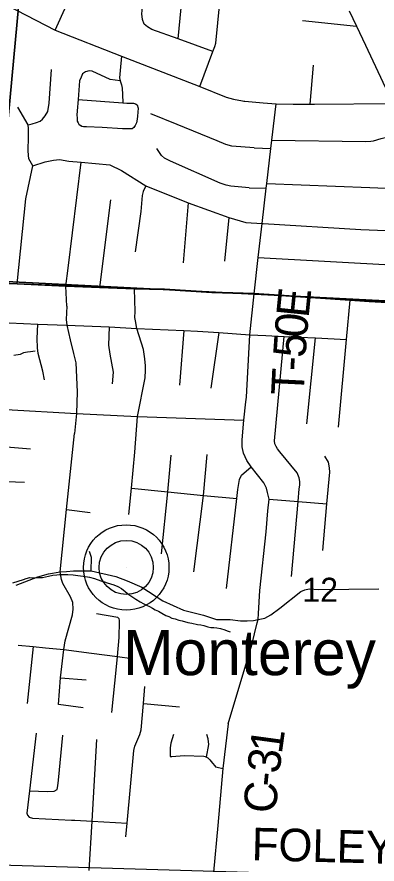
# Model space of a CAD drawing. Extents: x 0 to 34, y -2 to 22.
# Drawn here: x 5.292 to 5.919, y 16.731 to 18.207 of the extents above; entities that cross this region are included whole.
import ezdxf

# ---------------------------------------------------------------- set-up
doc = ezdxf.new("R2010")
doc.units = 0
for name, color, linetype in [('GM_X_City_Street', 7, 'Continuous'), ('GM_X_County_Road', 7, 'Continuous'), ('GM_X_County_Road_Text', 7, 'Continuous'), ('GM_X_Minor_River', 7, 'Continuous'), ('GM_X_Rail_Line', 7, 'Continuous'), ('GM_X_Section', 7, 'Continuous'), ('GM_X_Section_Text', 7, 'Continuous'), ('GM_X_State_Route', 7, 'Continuous'), ('GM_X_Township_Road', 7, 'Continuous'), ('GM_X_Township_Road_Text', 7, 'Continuous'), ('GM_X_Unincorporated', 7, 'Continuous'), ('GM_X_Unincorporated_Location', 7, 'Continuous'), ('GM_X_Unincorporated_Text', 7, 'Continuous')]:
    doc.layers.add(name, color=color, linetype=linetype)

msp = doc.modelspace()

# ---------------------------------------------------------------- linework, layer by layer
at = {"layer": 'GM_X_City_Street'}
for p, q in [((5.7895, 18.2011), (5.8832, 18.1912)), ((5.8026, 18.0553), (5.8087, 18.1234)), ((5.7049, 17.979), (5.7342, 17.9778)), ((5.6962, 17.9094), (5.7262, 17.9092)), ((5.7122, 17.7882), (6.0972, 17.7666)), ((5.5827, 17.6607), (5.5752, 17.5656)), ((5.7966, 17.4983), (5.8122, 17.6478))]:
    msp.add_line(p, q, dxfattribs=at)
for points in [[(5.7359, 17.9926), (5.8989, 17.9905), (5.9083, 17.9906), (5.9131, 17.9915), (5.9263, 17.9953), (5.9405, 17.999), (5.9682, 18.0148)], [(5.7271, 17.917), (5.9063, 17.9098), (5.9481, 17.9081), (5.9631, 17.9113), (5.9865, 17.9193), (6.0116, 17.9322)], [(5.6904, 17.8489), (5.7191, 17.8472), (5.7208, 17.8471), (5.8908, 17.8371), (6.0646, 17.83)], [(5.8521, 17.4924), (5.8661, 17.6452), (5.8723, 17.7135)], [(5.3792, 17.7031), (5.378, 17.6797), (5.3788, 17.6699), (5.3851, 17.6445), (5.3908, 17.6205), (5.3946, 17.6045), (5.397, 17.5536), (5.3959, 17.516), (5.3921, 17.4811)], [(5.4869, 17.3399), (5.4916, 17.3861), (5.4976, 17.4485), (5.5019, 17.5109), (5.5156, 17.5784), (5.5158, 17.5914), (5.5158, 17.5991), (5.5147, 17.6113), (5.5123, 17.6276), (5.501, 17.6644), (5.4984, 17.6774), (5.4976, 17.6834), (5.4978, 17.6939)], [(5.2288, 17.6765), (5.2532, 17.6752), (5.3283, 17.6719), (5.3788, 17.6699), (5.4526, 17.667), (5.501, 17.6644), (5.5827, 17.6607), (5.6067, 17.6595)], [(5.3403, 17.5748), (5.3374, 17.5901), (5.3292, 17.6209), (5.3281, 17.6308), (5.3275, 17.6466), (5.3283, 17.6719)], [(5.4526, 17.667), (5.4514, 17.6355), (5.4537, 17.6195), (5.4599, 17.588), (5.458, 17.5681)], [(5.7257, 17.6521), (5.7576, 17.6506), (5.8122, 17.6478), (5.8661, 17.6452)], [(5.7701, 17.232), (5.7815, 17.3629), (5.7835, 17.3849), (5.7844, 17.3911), (5.7848, 17.3975), (5.7834, 17.4041), (5.7803, 17.4127), (5.7496, 17.4494), (5.7455, 17.4543), (5.7434, 17.4585), (5.7414, 17.4634), (5.7406, 17.4686), (5.7576, 17.6506)], [(5.2736, 17.5232), (5.3959, 17.516), (5.5019, 17.5109), (5.6874, 17.5046)], [(5.544, 17.2712), (5.5546, 17.3795), (5.5606, 17.4432)], [(5.6004, 17.24), (5.6167, 17.3731), (5.6231, 17.4446)], [(5.8245, 17.2773), (5.8318, 17.3586), (5.8367, 17.4141), (5.8365, 17.4215), (5.8343, 17.4311), (5.8282, 17.442)], [(5.6571, 17.2108), (5.6752, 17.3677), (5.6768, 17.3839), (5.6796, 17.4012), (5.6834, 17.4086), (5.6998, 17.4229)], [(5.4916, 17.3861), (5.5546, 17.3795), (5.6167, 17.3731), (5.6752, 17.3677)], [(5.7313, 17.3667), (5.7815, 17.3629), (5.8318, 17.3586)]]:
    msp.add_lwpolyline(points, dxfattribs=at)
at = {"layer": 'GM_X_County_Road'}
for p, q in [((5.7432, 18.0559), (5.7729, 18.0556)), ((5.6417, 16.798), (5.6344, 16.7168))]:
    msp.add_line(p, q, dxfattribs=at)
for points in [[(5.192, 18.2677), (5.2571, 18.2366), (5.359, 18.1842), (5.4743, 18.1391), (5.6103, 18.0859), (5.6567, 18.0677), (5.6692, 18.064), (5.685, 18.0612)], [(5.685, 18.0612), (5.6869, 18.0608), (5.6892, 18.0604), (5.7208, 18.0578), (5.7432, 18.0559)], [(5.7729, 18.0556), (5.8026, 18.0553), (5.8104, 18.0553), (5.9463, 18.0565)], [(3.699, 17.9089), (3.9116, 17.8892), (3.995, 17.8815), (4.2231, 17.8563), (4.3328, 17.8445), (4.4265, 17.8357), (4.5119, 17.8261), (4.6385, 17.8125), (4.7305, 17.8021), (4.8416, 17.7902), (4.8921, 17.785), (5.1052, 17.7555), (5.1438, 17.7513), (5.1995, 17.7504), (5.2414, 17.7441), (5.2926, 17.7419), (5.3775, 17.7381), (5.4364, 17.7355), (5.4969, 17.7336), (5.5492, 17.7321), (5.6317, 17.7272), (5.6868, 17.7254)], [(5.6868, 17.7254), (5.7049, 17.7248), (5.7344, 17.7228)], [(5.7344, 17.7228), (5.8723, 17.7135), (5.9052, 17.7112), (6.0417, 17.704), (6.103, 17.7007), (6.1354, 17.7008)], [(5.2909, 17.2169), (5.3286, 17.2315), (5.3472, 17.2365), (5.3674, 17.2401), (5.3784, 17.2409), (5.3906, 17.2419), (5.4211, 17.2417), (5.4646, 17.2317), (5.4843, 17.2242), (5.5095, 17.2135), (5.5459, 17.1898), (5.5824, 17.1732), (5.617, 17.1645), (5.6397, 17.1568), (5.6636, 17.1572), (5.6816, 17.1547), (5.6826, 17.1547)], [(5.6826, 17.1547), (5.6927, 17.1546), (5.7038, 17.1555), (5.7122, 17.1571), (5.7237, 17.1596), (5.7341, 17.1651), (5.7499, 17.1765), (5.7866, 17.2056), (5.7936, 17.2089), (5.8012, 17.2102), (5.8175, 17.2094), (5.9224, 17.2104)], [(5.6599, 16.9751), (5.6505, 16.8973), (5.6417, 16.798)]]:
    msp.add_lwpolyline(points, dxfattribs=at)
at = {"layer": 'GM_X_Minor_River'}
for points in [[(5.324, 17.6245), (5.3156, 17.6236), (5.3107, 17.623), (5.3038, 17.6216), (5.298, 17.6191), (5.2869, 17.6171)], [(5.2849, 17.2211), (5.2941, 17.2239), (5.3037, 17.227), (5.3083, 17.2284), (5.3145, 17.2305), (5.3232, 17.2299), (5.3308, 17.2305), (5.3365, 17.2303), (5.3472, 17.2323), (5.3545, 17.234), (5.3614, 17.2349), (5.3663, 17.2352), (5.3808, 17.2355), (5.3899, 17.2349), (5.3982, 17.2339), (5.4073, 17.2325), (5.4183, 17.2307), (5.427, 17.2285), (5.4319, 17.2269), (5.4402, 17.224), (5.4447, 17.2227), (5.4492, 17.2211), (5.4609, 17.2177), (5.4681, 17.2148), (5.4741, 17.2112), (5.4804, 17.2061), (5.4871, 17.2006), (5.4938, 17.1958), (5.4994, 17.1926), (5.5065, 17.1879), (5.5133, 17.1846), (5.5178, 17.1818), (5.523, 17.1794), (5.5279, 17.177), (5.5328, 17.1738), (5.5384, 17.1713), (5.5444, 17.1681), (5.5515, 17.1641), (5.5568, 17.1621), (5.562, 17.1593), (5.5677, 17.158), (5.5741, 17.1559), (5.5798, 17.1546), (5.5896, 17.152), (5.5964, 17.1507), (5.6066, 17.1485), (5.6123, 17.1479), (5.6176, 17.1463), (5.6247, 17.1442), (5.6297, 17.1433), (5.635, 17.1431), (5.6403, 17.1422), (5.6463, 17.1413), (5.6539, 17.1388), (5.6584, 17.1375), (5.6633, 17.1355)]]:
    msp.add_lwpolyline(points, dxfattribs=at)
at = {"layer": 'GM_X_Rail_Line'}
for points in [[(6.0414, 17.7045), (5.905, 17.7117), (5.8721, 17.714), (5.7046, 17.7254), (5.6315, 17.7277), (5.5489, 17.7326), (5.4967, 17.7342), (5.4361, 17.736), (5.3773, 17.7386), (5.2924, 17.7424), (5.2412, 17.7447), (5.1993, 17.7509), (5.1435, 17.7518), (5.105, 17.756), (4.8918, 17.7856), (4.8414, 17.7907), (4.7302, 17.8027), (4.6382, 17.813), (4.5117, 17.8266), (4.4263, 17.8362), (4.3326, 17.8451)], [(4.3326, 17.8451), (4.4263, 17.8362), (4.5117, 17.8266), (4.6382, 17.813), (4.7302, 17.8027), (4.8414, 17.7907), (4.8918, 17.7856), (5.105, 17.756), (5.1435, 17.7518), (5.1993, 17.7509), (5.2412, 17.7447), (5.2924, 17.7424), (5.3773, 17.7386), (5.4361, 17.736), (5.4967, 17.7342), (5.5489, 17.7326), (5.6315, 17.7277), (5.7046, 17.7254), (5.8721, 17.714), (5.905, 17.7117), (6.0414, 17.7045)]]:
    msp.add_lwpolyline(points, dxfattribs=at)
at = {"layer": 'GM_X_Section'}
for points in [[(4.3356, 18.8839), (5.3451, 18.7715), (5.25, 17.7471), (4.2197, 17.8557)], [(6.3407, 18.6907), (6.241, 17.6971), (5.25, 17.7471), (5.3451, 18.7715)], [(5.25, 17.7471), (6.241, 17.6971), (6.1288, 16.703), (5.1427, 16.732)]]:
    msp.add_lwpolyline(points, close=True, dxfattribs=at)
at = {"layer": 'GM_X_State_Route'}
msp.add_lwpolyline([(5.8704, 18.218), (5.8832, 18.1912), (5.8991, 18.1582), (5.9463, 18.0565), (5.9507, 18.0481), (5.9682, 18.0148), (5.9885, 17.9762), (6.0116, 17.9322), (6.0145, 17.9267), (6.0324, 17.8927), (6.0646, 17.83), (6.0972, 17.7666), (6.1139, 17.7342), (6.1354, 17.7008), (6.1496, 17.6764), (6.1909, 17.6197), (6.2168, 17.5842), (6.2224, 17.5778), (6.2376, 17.5718), (6.2571, 17.5679), (6.2674, 17.5658)], dxfattribs=at)
at = {"layer": 'GM_X_Township_Road'}
for p, q in [((5.5728, 18.1695), (5.5852, 18.2943)), ((5.359, 18.1842), (5.3787, 18.2277)), ((5.5714, 18.0198), (5.5251, 18.0387)), ((5.4364, 17.7355), (5.4558, 17.8887)), ((5.5905, 17.8835), (5.5815, 17.7789)), ((5.6611, 17.8576), (5.6534, 17.7816)), ((5.3792, 17.7031), (5.3775, 17.7381)), ((5.4978, 17.6939), (5.4969, 17.7336)), ((5.6435, 17.6571), (5.6298, 17.5604)), ((5.6975, 17.6533), (5.7257, 17.6521)), ((5.1976, 17.4004), (5.3051, 17.3963)), ((5.3785, 17.3486), (5.4197, 17.3434)), ((5.3206, 17.1098), (5.3098, 17.0106)), ((5.3678, 17.0555), (5.4127, 17.0517)), ((5.5124, 17.0107), (5.5749, 17.0048))]:
    msp.add_line(p, q, dxfattribs=at)
for points in [[(5.6331, 18.147), (5.5728, 18.1695), (5.5272, 18.1857), (5.5195, 18.1902), (5.5138, 18.1951), (5.5105, 18.2027), (5.5098, 18.2126), (5.5107, 18.2244), (5.514, 18.255), (5.5122, 18.2628), (5.5089, 18.2677), (5.5041, 18.2723), (5.4968, 18.2756), (5.4906, 18.2768), (5.2927, 18.2891), (5.2844, 18.2867), (5.2781, 18.2824), (5.274, 18.2749), (5.2571, 18.2366), (5.2399, 18.2026), (5.2384, 18.1933), (5.2407, 18.1449), (5.2446, 18.0329)], [(5.6103, 18.0859), (5.6331, 18.147), (5.6343, 18.1503), (5.6367, 18.1558), (5.6387, 18.1619), (5.6483, 18.2627), (5.6509, 18.292)], [(5.4743, 18.1391), (5.4716, 18.1141), (5.471, 18.1011), (5.4716, 18.0959), (5.4731, 18.0924), (5.4741, 18.089), (5.4752, 18.083), (5.4762, 18.0723), (5.4766, 18.0576)], [(5.3118, 18.0196), (5.3184, 18.0209), (5.3265, 18.0234), (5.3325, 18.0256), (5.3368, 18.029), (5.3411, 18.0353), (5.3458, 18.0427), (5.348, 18.0569), (5.3526, 18.1158)], [(5.4716, 18.0959), (5.4544, 18.0986), (5.4232, 18.1126), (5.4179, 18.1133), (5.4117, 18.112), (5.4065, 18.1082), (5.4041, 18.1026), (5.4013, 18.0963), (5.3989, 18.0637), (5.3969, 18.0435), (5.3966, 18.0364), (5.3969, 18.0316), (5.3973, 18.0258), (5.3986, 18.0227), (5.4, 18.0203), (5.4028, 18.0181)], [(5.3989, 18.0637), (5.4766, 18.0576), (5.4834, 18.0573), (5.4895, 18.0573), (5.4935, 18.057), (5.4953, 18.0569), (5.4984, 18.056), (5.5017, 18.0543)], [(5.3122, 18.0028), (5.3123, 18.0066), (5.312, 18.0128), (5.3118, 18.0196), (5.2936, 18.05)], [(5.5017, 18.0543), (5.503, 18.0485), (5.5018, 18.0344), (5.5013, 18.0291), (5.5003, 18.023), (5.498, 18.0183), (5.4956, 18.0145), (5.4927, 18.0123), (5.4888, 18.0124), (5.4839, 18.0121), (5.4761, 18.0122)], [(5.7049, 17.7248), (5.7122, 17.7882), (5.7191, 17.8472), (5.7262, 17.9092), (5.7271, 17.917), (5.7342, 17.9778), (5.7359, 17.9926), (5.7432, 18.0559)], [(5.4761, 18.0122), (5.4407, 18.0147), (5.4135, 18.0157), (5.4081, 18.016), (5.4049, 18.0165), (5.4028, 18.0181)], [(5.7049, 17.979), (5.666, 17.9823), (5.6558, 17.9852), (5.6409, 17.9913), (5.5714, 18.0198)], [(5.2926, 17.7419), (5.3076, 17.8901), (5.3201, 17.9479), (5.3127, 17.96), (5.3116, 17.9732), (5.3121, 17.9989), (5.3122, 18.0028)], [(5.6962, 17.9094), (5.6645, 17.9122), (5.6562, 17.9143), (5.6457, 17.9176), (5.5596, 17.956), (5.5488, 17.961), (5.544, 17.9656), (5.5357, 17.9782)], [(5.3201, 17.9479), (5.3413, 17.9548), (5.3561, 17.9577), (5.3665, 17.9588), (5.3827, 17.9559), (5.404, 17.9541), (5.4537, 17.9498), (5.4742, 17.9397), (5.5167, 17.913), (5.5905, 17.8835), (5.6611, 17.8576), (5.6904, 17.8489)], [(5.3775, 17.7381), (5.3812, 17.7695), (5.404, 17.9541)], [(5.5167, 17.913), (5.512, 17.9032), (5.5102, 17.8959), (5.5078, 17.8685), (5.4979, 17.7982)], [(5.6909, 17.5362), (5.6918, 17.5446), (5.6975, 17.6533), (5.7049, 17.7248)], [(5.6067, 17.6595), (5.6435, 17.6571), (5.6975, 17.6533)], [(5.6998, 17.4229), (5.6922, 17.4341), (5.6866, 17.4469), (5.6841, 17.4582), (5.6842, 17.4704), (5.6874, 17.5046), (5.6909, 17.5362)], [(5.2712, 17.4896), (5.2702, 17.4749), (5.2701, 17.4683), (5.2704, 17.4604), (5.2737, 17.4582), (5.2811, 17.4575), (5.3157, 17.4548)], [(5.3674, 17.2401), (5.3785, 17.3486), (5.3921, 17.4811)], [(5.7127, 17.1672), (5.715, 17.2073), (5.7262, 17.3098), (5.7289, 17.3467), (5.7313, 17.3667), (5.7285, 17.3782), (5.7264, 17.3861), (5.722, 17.3952), (5.6998, 17.4229)], [(5.4211, 17.2417), (5.4218, 17.265), (5.4184, 17.2753)], [(5.4076, 17.0033), (5.3643, 17.0086), (5.3678, 17.0555), (5.3736, 17.1047), (5.3762, 17.12), (5.3889, 17.1654), (5.3902, 17.1752), (5.3892, 17.1866), (5.3855, 17.1966), (5.3722, 17.2197), (5.37, 17.2265), (5.3674, 17.2401)], [(5.4571, 16.9947), (5.4656, 17.0746), (5.4673, 17.0924), (5.4704, 17.1257), (5.471, 17.1538), (5.4708, 17.1556), (5.4699, 17.1582), (5.4688, 17.1596), (5.4679, 17.1603), (5.4309, 17.167)], [(5.6599, 16.9751), (5.7011, 17.1126), (5.7106, 17.1513), (5.7122, 17.1571), (5.7127, 17.1672)], [(5.2943, 17.1124), (5.3206, 17.1098), (5.3418, 17.1078)], [(5.3418, 17.1078), (5.3736, 17.1047), (5.4221, 17.0983), (5.4673, 17.0924), (5.4922, 17.0891)], [(5.482, 16.7781), (5.4841, 16.8019), (5.4955, 16.9284), (5.4976, 16.9359), (5.5061, 16.9566), (5.5086, 16.9645), (5.5124, 17.0107), (5.5148, 17.0402)], [(5.3254, 16.9587), (5.314, 16.8586), (5.3094, 16.8192), (5.3104, 16.8157), (5.3137, 16.8126), (5.319, 16.8109), (5.387, 16.8072), (5.393, 16.8069)], [(5.314, 16.8586), (5.3455, 16.8571), (5.357, 16.8579), (5.3622, 16.8605), (5.3632, 16.8673), (5.3645, 16.8772), (5.3718, 16.9556)], [(5.5647, 16.9565), (5.5602, 16.9415), (5.5587, 16.9332), (5.5587, 16.9182), (5.5617, 16.9182), (5.5835, 16.9197), (5.6173, 16.9189), (5.62, 16.9182), (5.6224, 16.917), (5.6243, 16.9158), (5.6282, 16.9126), (5.6324, 16.9068), (5.6367, 16.9021), (5.6381, 16.9004), (5.6407, 16.8994), (5.6505, 16.8973)], [(5.6224, 16.917), (5.6264, 16.9392), (5.6249, 16.949), (5.6226, 16.9565)], [(5.4178, 16.7193), (5.4229, 16.8052), (5.4311, 16.9476)], [(5.393, 16.8069), (5.4229, 16.8052), (5.4841, 16.8019)]]:
    msp.add_lwpolyline(points, dxfattribs=at)
at = {"layer": 'GM_X_Unincorporated'}
for radius in [0.0744, 0.0472]:
    msp.add_circle((5.4824, 17.2477), radius, dxfattribs=at)
at = {"layer": 'GM_X_Unincorporated_Location'}
msp.add_line((5.4824, 17.2477), (5.4824, 17.2477), dxfattribs=at)

# ---------------------------------------------------------------- texts
at = {"layer": 'GM_X_County_Road_Text'}
for s, height, rotation, p in [('1', 0.0568, 82.2195, (5.7532, 16.9215)), ('3', 0.0568, 83.1235, (5.749, 16.887)), ('-', 0.0568, 84.0882, (5.7467, 16.864)), ('C', 0.0568, 85.1584, (5.7428, 16.8178)), ('FOLEY', 0.05682, 358.5154, (5.7004, 16.7374))]:
    msp.add_text(s, height=height, rotation=rotation, dxfattribs=at).set_placement(p)
at = {"layer": 'GM_X_Section_Text'}
msp.add_text('12', height=0.04186, rotation=0, dxfattribs=at).set_placement((5.789, 17.1879))
at = {"layer": 'GM_X_Township_Road_Text'}
for s, rotation, p in [('E', 84.2303, (5.7998, 17.6816)), ('0', 85.199, (5.7969, 17.647)), ('5', 86.107, (5.7946, 17.6123)), ('-', 86.8526, (5.7933, 17.5892)), ('T', 87.15, (5.7912, 17.5468))]:
    msp.add_text(s, height=0.0568, rotation=rotation, dxfattribs=at).set_placement(p)
at = {"layer": 'GM_X_Unincorporated_Text'}
msp.add_text('Monterey', height=0.07898, rotation=0, dxfattribs=at).set_placement((5.4769, 17.06))

doc.saveas('drawing.dxf')
